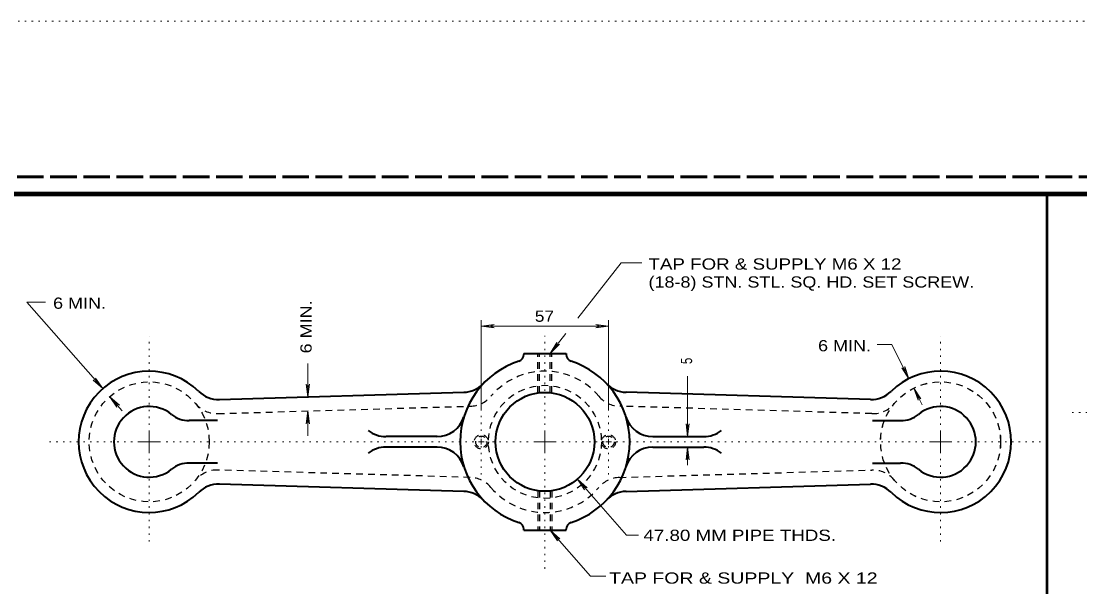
# Model space of a CAD drawing. Extents: x 312583 to 312854, y 144419 to 144597.
# Drawn here: x 312620.7 to 312692.5, y 144558.4 to 144596.8 of the extents above; entities that cross this region are included whole.
import ezdxf

# ---------------------------------------------------------------- set-up
doc = ezdxf.new("R2010")
doc.units = 0
doc.header["$LTSCALE"] = 0.3
for name, pattern in [('DOTTED', [1.5, 0.3, -1.2]), ('LONG_DASHED', [7.5, 6, -1.5]), ('SHORT_DASHED', [2.7, 1.5, -1.2])]:
    doc.linetypes.add(name, pattern=pattern)
for name, color, linetype, lineweight in [('1', 7, 'Continuous', 40), ('2', 7, 'Continuous', 13), ('62', 7, 'DOTTED', 13), ('63', 7, 'LONG_DASHED', 60)]:
    doc.layers.add(name, color=color, linetype=linetype, lineweight=lineweight)

msp = doc.modelspace()

# ---------------------------------------------------------------- linework, layer by layer
at = {"layer": '1', "lineweight": 53}
msp.add_line((312690.3095, 144476.2913), (312690.3095, 144585.0846), dxfattribs=at)
at = {"layer": '1'}
for p, q in [((312654.8121, 144574.2482), (312654.8121, 144574.1869)), ((312654.8121, 144574.2482), (312657.6871, 144574.2482)), ((312657.6871, 144574.2482), (312657.6871, 144574.1869)), ((312634.1734, 144571.1355), (312650.7487, 144571.6185)), ((312678.3334, 144571.1355), (312661.7581, 144571.6185)), ((312634.0354, 144569.6942), (312632.1264, 144569.6942)), ((312678.4714, 144569.6942), (312680.3727, 144569.6942)), ((312648.9317, 144568.6132), (312645.4741, 144568.6132)), ((312663.5751, 144568.6132), (312667.0327, 144568.6132)), ((312648.9317, 144567.9002), (312645.4741, 144567.9002)), ((312663.5751, 144567.9002), (312667.0327, 144567.9002)), ((312634.0354, 144566.8192), (312632.1264, 144566.8192)), ((312678.4714, 144566.8192), (312680.3727, 144566.8192)), ((312650.7487, 144564.8949), (312634.1734, 144565.3855)), ((312661.7581, 144564.8949), (312678.3334, 144565.3855)), ((312654.8121, 144562.2729), (312654.8121, 144562.3342)), ((312654.8121, 144562.2729), (312657.6871, 144562.2729)), ((312657.6871, 144562.2729), (312657.6871, 144562.3342))]:
    msp.add_line(p, q, dxfattribs=at)
at = {"layer": '1', "linetype": 'SHORT_DASHED', "lineweight": 25}
for p, q in [((312655.7704, 144571.5802), (312655.7704, 144574.2482)), ((312655.8854, 144571.5802), (312655.8854, 144574.2482)), ((312656.6137, 144571.5802), (312656.6137, 144574.2482)), ((312656.7287, 144571.5802), (312656.7287, 144574.2482)), ((312634.0814, 144570.1695), (312651.1857, 144570.6755)), ((312678.4254, 144570.1695), (312661.3211, 144570.6755)), ((312651.1857, 144565.8455), (312634.0814, 144566.3439)), ((312661.3211, 144565.8455), (312678.4254, 144566.3439)), ((312655.7704, 144564.9409), (312655.7704, 144562.2652)), ((312655.8854, 144564.9409), (312655.8854, 144562.2652)), ((312656.6137, 144564.9409), (312656.6137, 144562.2652)), ((312656.7287, 144564.9409), (312656.7287, 144562.2652))]:
    msp.add_line(p, q, dxfattribs=at)
at = {"layer": '1', "lineweight": 158}
msp.add_lwpolyline([(312616.5, 144423.1446), (312616.5, 144585.0846), (312849, 144585.0846)], dxfattribs=at)
at = {"layer": '1', "linetype": 'SHORT_DASHED', "lineweight": 25}
for centre, radius in [((312629.4162, 144568.2567), 4.0729), ((312656.2496, 144568.2567), 3.8319), ((312683.0829, 144568.2567), 4.0729), ((312683.0829, 144568.2567), 4.0722), ((312651.9371, 144568.2567), 0.4792), ((312651.9371, 144568.2567), 0.3833), ((312660.5621, 144568.2567), 0.4792), ((312660.5621, 144568.2567), 0.3833)]:
    msp.add_circle(centre, radius, dxfattribs=at)
at = {"layer": '1'}
msp.add_circle((312656.2496, 144568.2567), 3.3542, dxfattribs=at)
for centre, radius, start, end in [((312654.3329, 144574.1837), 0.4792, 287.92021, 0), ((312658.1662, 144574.1837), 0.4792, 180.07545, 252.31321), ((312656.2496, 144568.2567), 5.75, 107.93968, 252.06032), ((312656.2496, 144568.2567), 5.75, 287.93968, 72.06032), ((312629.4162, 144568.2567), 4.7917, 45.58331, 314.41669), ((312683.0829, 144568.2567), 4.7917, 225.58331, 134.41669), ((312650.6882, 144573.5339), 1.9167, 271.68019, 316.50201), ((312661.811, 144573.5339), 1.9167, 223.49799, 268.31981), ((312634.1118, 144573.0477), 1.9167, 225.57624, 271.68173), ((312678.3873, 144573.0477), 1.9167, 268.31827, 314.42376), ((312629.4162, 144568.2567), 2.3958, 51.03954, 308.96046), ((312683.0829, 144568.2567), 2.3958, 231.03954, 128.96046), ((312632.1268, 144571.6109), 1.9167, 231.05756, 270), ((312648.9276, 144570.5299), 1.9167, 270.00753, 342.76455), ((312663.5715, 144570.5299), 1.9167, 197.23545, 269.99247), ((312680.3723, 144571.6109), 1.9167, 270, 308.94244), ((312645.4705, 144570.5299), 1.9167, 231.22582, 269.99247), ((312667.0286, 144570.5299), 1.9167, 270.00753, 308.77418), ((312645.4705, 144565.9835), 1.9167, 90.00753, 128.66619), ((312648.9276, 144565.9835), 1.9167, 17.24751, 90), ((312663.5715, 144565.9835), 1.9167, 90, 162.75249), ((312667.0286, 144565.9835), 1.9167, 51.33381, 89.99247), ((312632.1268, 144564.9025), 1.9167, 90, 128.94244), ((312680.3723, 144564.9025), 1.9167, 51.05756, 90), ((312634.1118, 144563.4657), 1.9167, 88.31827, 134.42376), ((312678.3873, 144563.4657), 1.9167, 45.57624, 91.68173), ((312650.6882, 144562.9795), 1.9167, 43.49799, 88.31981), ((312661.811, 144562.9795), 1.9167, 91.68019, 136.50201), ((312654.3329, 144562.3297), 0.4792, 0, 72.07979), ((312658.1662, 144562.3297), 0.4792, 107.92021, 180)]:
    msp.add_arc(centre, radius, start, end, dxfattribs=at)
at = {"layer": '1', "linetype": 'SHORT_DASHED', "lineweight": 25}
for centre, radius, start, end in [((312656.2496, 144568.2567), 4.7917, 40.19869, 139.80132), ((312651.1262, 144572.5872), 1.9167, 271.68032, 319.79428), ((312661.3729, 144572.5872), 1.9167, 220.20572, 268.31967), ((312634.0222, 144572.0856), 1.9167, 219.73621, 271.68136), ((312678.4769, 144572.0856), 1.9167, 268.31864, 320.26379), ((312634.0222, 144564.4278), 1.9167, 88.31864, 140.26379), ((312678.4769, 144564.4278), 1.9167, 39.73621, 91.68136), ((312651.1262, 144563.9262), 1.9167, 40.20572, 88.31968), ((312661.3729, 144563.9262), 1.9167, 91.68032, 139.79428), ((312656.2496, 144568.2567), 4.7917, 220.19869, 319.80132)]:
    msp.add_arc(centre, radius, start, end, dxfattribs=at)
at = {"layer": '2'}
for p, q in [((312658.4921, 144576.6479), (312661.4207, 144580.3892)), ((312661.4207, 144580.3892), (312662.8161, 144580.3892)), ((312626.2614, 144571.8639), (312621.1232, 144577.7275)), ((312622.391, 144577.7275), (312621.1232, 144577.7275)), ((312651.9371, 144570.4609), (312651.9371, 144576.5099)), ((312651.9371, 144576.1035), (312652.8034, 144576.2109)), ((312651.9371, 144576.1035), (312660.5621, 144576.1035)), ((312651.9371, 144576.1035), (312652.8034, 144575.9962)), ((312652.8034, 144576.2109), (312652.5274, 144576.1035)), ((312652.8034, 144575.9962), (312652.5274, 144576.1035)), ((312659.6957, 144576.2109), (312659.9717, 144576.1035)), ((312660.5621, 144576.1035), (312659.6957, 144576.2109)), ((312659.6957, 144575.9962), (312659.9717, 144576.1035)), ((312660.5621, 144576.1035), (312659.6957, 144575.9962)), ((312660.5621, 144570.4609), (312660.5621, 144576.5099)), ((312656.6137, 144574.2482), (312657.6717, 144575.5975)), ((312656.6137, 144574.2482), (312657.0661, 144574.9995)), ((312656.6137, 144574.2482), (312657.2347, 144574.8692)), ((312657.0661, 144574.9995), (312656.9817, 144574.7159)), ((312657.2347, 144574.8692), (312656.9817, 144574.7159)), ((312679.7747, 144574.8615), (312678.7857, 144574.8615)), ((312680.9401, 144572.5385), (312679.7747, 144574.8615)), ((312640.1687, 144571.3119), (312640.1687, 144573.5735)), ((312680.4571, 144573.2669), (312680.6717, 144573.0675)), ((312680.9401, 144572.5385), (312680.4571, 144573.2669)), ((312680.6487, 144573.3665), (312680.6717, 144573.0675)), ((312680.9401, 144572.5385), (312680.6487, 144573.3665)), ((312625.6097, 144572.4465), (312625.8704, 144572.3085)), ((312626.2614, 144571.8639), (312625.6097, 144572.4465)), ((312625.7707, 144572.5845), (312625.8704, 144572.3085)), ((312626.2614, 144571.8639), (312625.7707, 144572.5845)), ((312665.9287, 144568.6132), (312665.9287, 144572.7196)), ((312640.0614, 144572.1782), (312640.1687, 144571.9022)), ((312640.1687, 144571.3119), (312640.0614, 144572.1782)), ((312640.2761, 144572.1782), (312640.1687, 144571.9022)), ((312640.1687, 144571.3119), (312640.2761, 144572.1782)), ((312681.8294, 144570.7752), (312681.2621, 144571.9022)), ((312681.2621, 144571.9022), (312681.5534, 144571.0742)), ((312681.2621, 144571.9022), (312681.7451, 144571.1739)), ((312627.5801, 144570.3535), (312626.7367, 144571.3195)), ((312626.7367, 144571.3195), (312627.2274, 144570.5989)), ((312626.7367, 144571.3195), (312627.3884, 144570.7369)), ((312681.5534, 144571.0742), (312681.5227, 144571.3732)), ((312681.7451, 144571.1739), (312681.5227, 144571.3732)), ((312627.2274, 144570.5989), (312627.1277, 144570.8749)), ((312627.3884, 144570.7369), (312627.1277, 144570.8749)), ((312640.1687, 144570.3535), (312640.0614, 144569.4872)), ((312640.1687, 144568.6745), (312640.1687, 144570.3535)), ((312640.1687, 144570.3535), (312640.2761, 144569.4872)), ((312640.0614, 144569.4872), (312640.1687, 144569.7632)), ((312640.2761, 144569.4872), (312640.1687, 144569.7632)), ((312629.4201, 144568.2605), (312629.4201, 144569.0272)), ((312656.2534, 144568.2605), (312656.2534, 144569.0272)), ((312665.8214, 144569.4795), (312665.9287, 144569.2035)), ((312665.9287, 144568.6132), (312665.8214, 144569.4795)), ((312666.0361, 144569.4795), (312665.9287, 144569.2035)), ((312665.9287, 144568.6132), (312666.0361, 144569.4795)), ((312683.0867, 144568.2605), (312683.0867, 144569.0272)), ((312629.4201, 144568.2605), (312628.6534, 144568.2605)), ((312629.4201, 144568.2605), (312629.4201, 144567.4939)), ((312629.4201, 144568.2605), (312630.1867, 144568.2605)), ((312651.9371, 144568.2605), (312651.7454, 144568.2605)), ((312651.9371, 144568.2605), (312651.9371, 144568.4522)), ((312651.9371, 144568.2605), (312651.9371, 144568.0689)), ((312651.9371, 144568.2605), (312652.1287, 144568.2605)), ((312656.2534, 144568.2605), (312655.4867, 144568.2605)), ((312656.2534, 144568.2605), (312656.2534, 144567.4939)), ((312656.2534, 144568.2605), (312657.0201, 144568.2605)), ((312660.5621, 144568.2605), (312660.3704, 144568.2605)), ((312660.5621, 144568.2605), (312660.5621, 144568.4522)), ((312660.5621, 144568.2605), (312660.5621, 144568.0689)), ((312660.5621, 144568.2605), (312660.7537, 144568.2605)), ((312683.0867, 144568.2605), (312682.3201, 144568.2605)), ((312683.0867, 144568.2605), (312683.0867, 144567.4939)), ((312683.0867, 144568.2605), (312683.8534, 144568.2605)), ((312665.9287, 144567.9002), (312665.8214, 144567.0339)), ((312665.9287, 144566.6659), (312665.9287, 144567.9002)), ((312665.9287, 144567.9002), (312666.0361, 144567.0339)), ((312665.8214, 144567.0339), (312665.9287, 144567.3099)), ((312666.0361, 144567.0339), (312665.9287, 144567.3099)), ((312658.4537, 144565.7305), (312661.7811, 144561.9202)), ((312658.4537, 144565.7305), (312658.9444, 144565.0022)), ((312658.4537, 144565.7305), (312659.1054, 144565.1479)), ((312658.9444, 144565.0022), (312658.8447, 144565.2859)), ((312659.1054, 144565.1479), (312658.8447, 144565.2859)), ((312656.6137, 144562.2652), (312659.3431, 144559.1372)), ((312656.6137, 144562.2652), (312657.1044, 144561.5445)), ((312656.6137, 144562.2652), (312657.2654, 144561.6825)), ((312657.1044, 144561.5445), (312657.0047, 144561.8205)), ((312657.2654, 144561.6825), (312657.0047, 144561.8205)), ((312662.6014, 144561.9202), (312661.7811, 144561.9202)), ((312660.3704, 144559.1372), (312659.3431, 144559.1372))]:
    msp.add_line(p, q, dxfattribs=at)
at = {"layer": '2', "linetype": 'DOTTED'}
for p, q in [((312629.4201, 144569.4105), (312629.4201, 144575.4059)), ((312656.2534, 144569.4105), (312656.2534, 144575.4519)), ((312683.0867, 144569.4105), (312683.0867, 144575.4059)), ((312651.9371, 144568.5442), (312651.9371, 144570.4609)), ((312660.5621, 144568.5442), (312660.5621, 144570.4609)), ((312698.0847, 144570.2545), (312691.936, 144570.2545)), ((312628.2701, 144568.2605), (312622.4511, 144568.2605)), ((312630.5701, 144568.2605), (312638.2367, 144568.2605)), ((312655.1034, 144568.2605), (312638.2367, 144568.2605)), ((312657.4034, 144568.2605), (312674.2701, 144568.2605)), ((312681.9367, 144568.2605), (312674.2701, 144568.2605)), ((312684.2367, 144568.2605), (312689.9101, 144568.2605)), ((312651.9371, 144567.9692), (312651.9371, 144566.0525)), ((312660.5621, 144567.9692), (312660.5621, 144566.0525)), ((312629.4201, 144567.1105), (312629.4201, 144561.1689)), ((312656.2534, 144567.1105), (312656.2534, 144559.4439)), ((312683.0867, 144567.1105), (312683.0867, 144561.1689))]:
    msp.add_line(p, q, dxfattribs=at)
at = {"layer": '62'}
msp.add_line((312601.2, 144596.7846), (312853.5, 144596.7846), dxfattribs=at)
at = {"layer": '63'}
msp.add_line((312851.75, 144586.2246), (312583.526, 144586.2246), dxfattribs=at)

# ---------------------------------------------------------------- texts
at = {"layer": '2'}
for s, width, p in [('TAP FOR & SUPPLY M6 X 12', 1.25, (312663.273, 144579.9359)), ('(18-8) STN. STL. SQ. HD. SET SCREW.', 1.2, (312663.273, 144578.7159)), ('6 MIN.', 1.2, (312622.8951, 144577.2815)), ('57 ', 1.15, (312655.5667, 144576.3963)), ('6 MIN.', 1.2, (312674.7742, 144574.3953)), ('47.80 MM PIPE THDS.', 1.25, (312662.9311, 144561.5402)), ('TAP FOR & SUPPLY  M6 X 12', 1.3, (312660.6004, 144558.6389))]:
    msp.add_text(s, height=0.76, dxfattribs=dict(at, width=width)).set_placement(p)
for s, width, p in [('6 MIN.', 1.2, (312640.4282, 144574.2552)), ('5', 0.75, (312666.2329, 144573.5344))]:
    msp.add_text(s, height=0.76, rotation=90, dxfattribs=dict(at, width=width)).set_placement(p)

doc.saveas('drawing.dxf')
